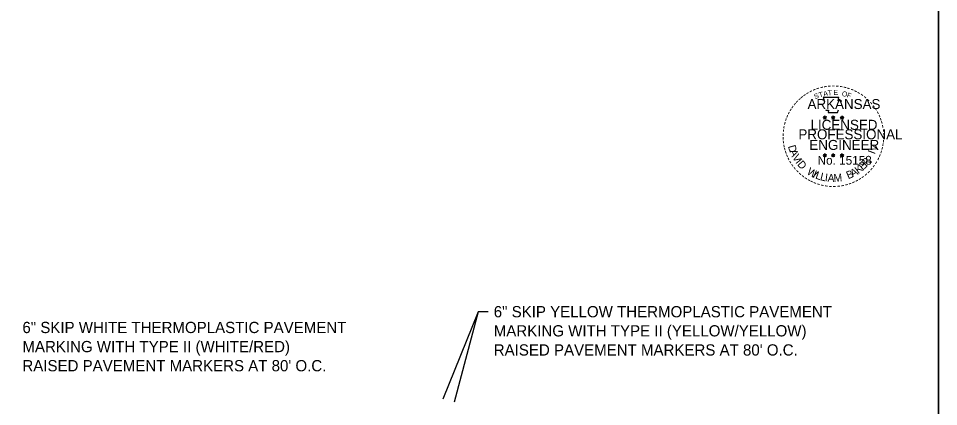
# Model space of a CAD drawing. Extents: x 1373096 to 1373266, y 381130 to 381790.
# Drawn here: x 1373174 to 1373266, y 381529.2 to 381568 of the extents above; entities that cross this region are included whole.
import ezdxf

# ---------------------------------------------------------------- set-up
doc = ezdxf.new("R2010")
doc.units = 0
for name, color, linetype in [('Default', 7, 'Continuous'), ('DSN_DRFT_Junk-No-Plot', 7, 'Continuous'), ('R_Border PE', 7, 'Continuous')]:
    doc.layers.add(name, color=color, linetype=linetype)

msp = doc.modelspace()

# ---------------------------------------------------------------- linework, layer by layer
at = {"layer": 'Default'}
for p, q in [((1373219.95, 381538.656), (1373216.424, 381529.917)), ((1373219.95, 381538.656), (1373217.551, 381529.618)), ((1373220.95, 381538.656), (1373219.95, 381538.656))]:
    msp.add_line(p, q, dxfattribs=at)
msp.add_lwpolyline([(1373095.974, 381570.174), (1373095.974, 381460.174), (1373265.974, 381460.174), (1373265.974, 381570.174)], close=True, dxfattribs=at)
at = {"layer": 'DSN_DRFT_Junk-No-Plot'}
for points in [[(1373095.974, 381570.174), (1373265.974, 381570.174), (1373265.974, 381460.174), (1373095.974, 381460.174)], [(1373095.974, 381570.174), (1373095.974, 381460.174), (1373265.974, 381460.174), (1373265.974, 381570.174)]]:
    msp.add_lwpolyline(points, close=True, dxfattribs=at)
at = {"layer": 'R_Border PE'}
for p, q in [((1373254.429, 381558.13), (1373254.603, 381558.074)), ((1373254.429, 381558.13), (1373254.555, 381558.107)), ((1373254.429, 381558.13), (1373254.547, 381558.069)), ((1373254.495, 381557.926), (1373254.603, 381558.074)), ((1373254.495, 381557.926), (1373254.558, 381558.048)), ((1373254.495, 381557.926), (1373254.602, 381558.034)), ((1373254.603, 381558.257), (1373254.583, 381558.131)), ((1373254.71, 381557.926), (1373254.602, 381558.033)), ((1373254.603, 381558.074), (1373254.603, 381558.257)), ((1373254.603, 381558.257), (1373254.628, 381558.132)), ((1373254.777, 381558.13), (1373254.603, 381558.074)), ((1373254.71, 381557.926), (1373254.603, 381558.074)), ((1373254.777, 381558.13), (1373254.634, 381558.105)), ((1373254.71, 381557.926), (1373254.641, 381558.071)), ((1373254.777, 381558.13), (1373254.675, 381558.079)), ((1373255.264, 381558.13), (1373255.438, 381558.074)), ((1373255.264, 381558.13), (1373255.39, 381558.107)), ((1373255.264, 381558.13), (1373255.382, 381558.069)), ((1373255.33, 381557.926), (1373255.438, 381558.074)), ((1373255.33, 381557.926), (1373255.393, 381558.048)), ((1373255.33, 381557.926), (1373255.437, 381558.034)), ((1373255.438, 381558.257), (1373255.418, 381558.131)), ((1373255.545, 381557.926), (1373255.437, 381558.033)), ((1373255.438, 381558.074), (1373255.438, 381558.257)), ((1373255.438, 381558.257), (1373255.463, 381558.132)), ((1373255.612, 381558.13), (1373255.438, 381558.074)), ((1373255.545, 381557.926), (1373255.438, 381558.074)), ((1373255.612, 381558.13), (1373255.469, 381558.105)), ((1373255.545, 381557.926), (1373255.476, 381558.071)), ((1373255.612, 381558.13), (1373255.51, 381558.079)), ((1373256.146, 381558.124), (1373256.32, 381558.068)), ((1373256.146, 381558.124), (1373256.272, 381558.101)), ((1373256.146, 381558.124), (1373256.264, 381558.063)), ((1373256.212, 381557.92), (1373256.32, 381558.068)), ((1373256.212, 381557.92), (1373256.275, 381558.042)), ((1373256.212, 381557.92), (1373256.319, 381558.028)), ((1373256.32, 381558.251), (1373256.3, 381558.125)), ((1373256.427, 381557.92), (1373256.319, 381558.027)), ((1373256.32, 381558.068), (1373256.32, 381558.251)), ((1373256.32, 381558.251), (1373256.345, 381558.126)), ((1373256.494, 381558.124), (1373256.32, 381558.068)), ((1373256.427, 381557.92), (1373256.32, 381558.068)), ((1373256.494, 381558.124), (1373256.351, 381558.099)), ((1373256.427, 381557.92), (1373256.358, 381558.065)), ((1373256.494, 381558.124), (1373256.392, 381558.073)), ((1373254.427, 381554.343), (1373254.601, 381554.288)), ((1373254.427, 381554.343), (1373254.553, 381554.321)), ((1373254.427, 381554.343), (1373254.545, 381554.282)), ((1373254.493, 381554.139), (1373254.601, 381554.288)), ((1373254.493, 381554.139), (1373254.556, 381554.261)), ((1373254.493, 381554.139), (1373254.6, 381554.248)), ((1373254.601, 381554.47), (1373254.581, 381554.344)), ((1373254.708, 381554.139), (1373254.6, 381554.246)), ((1373254.601, 381554.288), (1373254.601, 381554.47)), ((1373254.601, 381554.47), (1373254.626, 381554.345)), ((1373254.775, 381554.343), (1373254.601, 381554.288)), ((1373254.708, 381554.139), (1373254.601, 381554.288)), ((1373254.775, 381554.343), (1373254.632, 381554.319)), ((1373254.708, 381554.139), (1373254.639, 381554.285)), ((1373254.775, 381554.343), (1373254.673, 381554.292)), ((1373255.261, 381554.343), (1373255.436, 381554.288)), ((1373255.261, 381554.343), (1373255.388, 381554.321)), ((1373255.261, 381554.343), (1373255.38, 381554.282)), ((1373255.328, 381554.139), (1373255.436, 381554.288)), ((1373255.328, 381554.139), (1373255.391, 381554.261)), ((1373255.328, 381554.139), (1373255.435, 381554.248)), ((1373255.436, 381554.47), (1373255.415, 381554.344)), ((1373255.542, 381554.139), (1373255.435, 381554.246)), ((1373255.436, 381554.288), (1373255.436, 381554.47)), ((1373255.436, 381554.47), (1373255.46, 381554.345)), ((1373255.609, 381554.343), (1373255.436, 381554.288)), ((1373255.542, 381554.139), (1373255.436, 381554.288)), ((1373255.609, 381554.343), (1373255.466, 381554.319)), ((1373255.542, 381554.139), (1373255.474, 381554.285)), ((1373255.609, 381554.343), (1373255.507, 381554.292)), ((1373256.145, 381554.338), (1373256.319, 381554.283)), ((1373256.145, 381554.338), (1373256.271, 381554.316)), ((1373256.145, 381554.338), (1373256.263, 381554.277)), ((1373256.211, 381554.134), (1373256.319, 381554.283)), ((1373256.211, 381554.134), (1373256.274, 381554.256)), ((1373256.211, 381554.134), (1373256.318, 381554.243)), ((1373256.319, 381554.465), (1373256.299, 381554.339)), ((1373256.426, 381554.134), (1373256.318, 381554.241)), ((1373256.319, 381554.283), (1373256.319, 381554.465)), ((1373256.319, 381554.465), (1373256.344, 381554.34)), ((1373256.493, 381554.338), (1373256.319, 381554.283)), ((1373256.426, 381554.134), (1373256.319, 381554.283)), ((1373256.493, 381554.338), (1373256.35, 381554.314)), ((1373256.426, 381554.134), (1373256.357, 381554.28)), ((1373256.493, 381554.338), (1373256.391, 381554.287))]:
    msp.add_line(p, q, dxfattribs=at)
for points in [[(1373254.449, 381560.069), (1373254.584, 381559.655)], [(1373256.205, 381559.608), (1373256.276, 381559.75), (1373255.933, 381559.738), (1373256.007, 381560.069), (1373254.449, 381560.069)], [(1373254.695, 381558.857), (1373254.695, 381558.814), (1373254.977, 381558.804), (1373254.95, 381558.568), (1373255.885, 381558.568), (1373255.985, 381558.836)], [(1373254.603, 381558.257), (1373254.71, 381557.926), (1373254.429, 381558.13), (1373254.777, 381558.13), (1373254.495, 381557.926), (1373254.603, 381558.257)], [(1373255.438, 381558.257), (1373255.545, 381557.926), (1373255.264, 381558.13), (1373255.612, 381558.13), (1373255.33, 381557.926), (1373255.438, 381558.257)], [(1373256.32, 381558.251), (1373256.427, 381557.92), (1373256.146, 381558.124), (1373256.494, 381558.124), (1373256.212, 381557.92), (1373256.32, 381558.251)], [(1373254.601, 381554.47), (1373254.708, 381554.139), (1373254.427, 381554.343), (1373254.775, 381554.343), (1373254.493, 381554.139), (1373254.601, 381554.47)], [(1373255.436, 381554.47), (1373255.542, 381554.139), (1373255.261, 381554.343), (1373255.609, 381554.343), (1373255.328, 381554.139), (1373255.436, 381554.47)], [(1373256.319, 381554.465), (1373256.426, 381554.134), (1373256.145, 381554.338), (1373256.493, 381554.338), (1373256.211, 381554.134), (1373256.319, 381554.465)]]:
    msp.add_lwpolyline(points, dxfattribs=at)
for centre, radius in [((1373254.603, 381558.074), 0.0861), ((1373254.603, 381558.074), 0.0723), ((1373254.603, 381558.074), 0.0579), ((1373254.603, 381558.074), 0.0495), ((1373254.603, 381558.074), 0.0374), ((1373254.603, 381558.074), 0.0248), ((1373254.603, 381558.074), 0.0148), ((1373255.438, 381558.074), 0.0861), ((1373255.438, 381558.074), 0.0723), ((1373255.438, 381558.074), 0.0579), ((1373255.438, 381558.074), 0.0495), ((1373255.438, 381558.074), 0.0374), ((1373255.438, 381558.074), 0.0248), ((1373255.438, 381558.074), 0.0148), ((1373256.32, 381558.068), 0.0861), ((1373256.32, 381558.068), 0.0723), ((1373256.32, 381558.068), 0.0579), ((1373256.32, 381558.068), 0.0495), ((1373256.32, 381558.068), 0.0374), ((1373256.32, 381558.068), 0.0248), ((1373256.32, 381558.068), 0.0148), ((1373254.601, 381554.287), 0.0861), ((1373254.601, 381554.287), 0.0723), ((1373254.601, 381554.287), 0.0579), ((1373254.601, 381554.287), 0.0495), ((1373254.601, 381554.287), 0.0374), ((1373254.601, 381554.287), 0.0248), ((1373254.601, 381554.287), 0.0148), ((1373255.435, 381554.287), 0.0861), ((1373255.435, 381554.287), 0.0723), ((1373255.435, 381554.287), 0.0579), ((1373255.435, 381554.287), 0.0495), ((1373255.435, 381554.287), 0.0374), ((1373255.435, 381554.287), 0.0248), ((1373255.435, 381554.287), 0.0148), ((1373256.319, 381554.282), 0.0861), ((1373256.319, 381554.282), 0.0723), ((1373256.319, 381554.282), 0.0579), ((1373256.319, 381554.282), 0.0495), ((1373256.319, 381554.282), 0.0374), ((1373256.319, 381554.282), 0.0248), ((1373256.319, 381554.282), 0.0148)]:
    msp.add_circle(centre, radius, dxfattribs=at)

# ---------------------------------------------------------------- texts
at = {"layer": 'Default'}
for s, p in [('6" SKIP YELLOW THERMOPLASTIC PAVEMENT', (1373221.513, 381538.094)), ('6" SKIP WHITE THERMOPLASTIC PAVEMENT', (1373174.403, 381536.517)), ('MARKING WITH TYPE II (YELLOW/YELLOW)', (1373221.513, 381536.181)), ('MARKING WITH TYPE II (WHITE/RED)', (1373174.403, 381534.605)), ("RAISED PAVEMENT MARKERS AT 80' O.C.", (1373221.513, 381534.269)), ("RAISED PAVEMENT MARKERS AT 80' O.C.", (1373174.403, 381532.693))]:
    msp.add_text(s, height=1.125, dxfattribs=at).set_placement(p)
at = {"layer": 'R_Border PE'}
for s, height, rotation, p in [('-', 0.8, 19.17608, (1373253.823, 381560.632)), ('-', 0.8, 13.63015, (1373254.198, 381560.753)), ('-', 0.8, 10.21935, (1373254.537, 381560.834)), ('-', 0.8, 5.89682, (1373254.901, 381560.889)), ('-', 0.8, 0.18623, (1373255.287, 381560.925)), ('-', 0.8, 357.74304, (1373255.649, 381560.918)), ('-', 0.8, 352.16172, (1373256.021, 381560.89)), ('-', 0.8, 347.20489, (1373256.38, 381560.833)), ('-', 0.8, 342.3362, (1373256.698, 381560.756)), ('-', 0.8, 38.95066, (1373252.364, 381559.768)), ('-', 0.8, 36.23174, (1373252.602, 381559.957)), ('-', 0.8, 34.06357, (1373252.891, 381560.154)), ('-', 0.8, 28.79182, (1373253.189, 381560.339)), ('-', 0.8, 24.30721, (1373253.506, 381560.498)), ('S', 0.5, 21.59401, (1373253.626, 381559.908)), ('T', 0.5, 16.4036, (1373254.083, 381560.073)), ('A', 0.5, 11.21318, (1373254.496, 381560.199)), ('T', 0.5, 6.02276, (1373254.921, 381560.282)), ('E', 0.5, 0.83234, (1373255.473, 381560.337)), ('O', 0.5, 350.4515, (1373256.275, 381560.232)), ('F', 0.5, 340.07066, (1373256.752, 381560.118)), ('-', 0.8, 337.85509, (1373257.065, 381560.644)), ('-', 0.8, 334.12109, (1373257.381, 381560.509)), ('-', 0.8, 329.64089, (1373257.67, 381560.367)), ('-', 0.8, 325.86266, (1373257.992, 381560.187)), ('-', 0.8, 320.52971, (1373258.297, 381559.974)), ('-', 0.8, 54.23247, (1373251.515, 381558.794)), ('-', 0.8, 50.61418, (1373251.722, 381559.077)), ('-', 0.8, 48.42305, (1373251.923, 381559.32)), ('-', 0.8, 42.96224, (1373252.147, 381559.559)), ('-', 0.8, 315.57859, (1373258.596, 381559.73)), ('-', 0.8, 309.87973, (1373258.881, 381559.455)), ('-', 0.8, 306.65218, (1373259.143, 381559.154)), ('-', 0.8, 67.77427, (1373251.067, 381557.918)), ('-', 0.8, 62.87135, (1373251.196, 381558.223)), ('-', 0.8, 58.07063, (1373251.353, 381558.53)), ('-', 0.7, 303.67529, (1373259.386, 381558.87)), ('-', 0.8, 299.66835, (1373259.546, 381558.566)), ('-', 0.8, 294.66279, (1373259.708, 381558.26)), ('-', 0.8, 75.46096, (1373250.859, 381557.246)), ('-', 0.8, 72.39447, (1373250.957, 381557.603)), ('-', 0.8, 290.57283, (1373259.836, 381557.972)), ('-', 0.8, 285.12326, (1373259.953, 381557.682)), ('-', 0.8, 89.06224, (1373250.742, 381556.193)), ('-', 0.8, 85.18634, (1373250.755, 381556.544)), ('-', 0.8, 81.20126, (1373250.793, 381556.889)), ('-', 0.8, 280.54934, (1373260.053, 381557.311)), ('-', 0.8, 276.59616, (1373260.134, 381556.927)), ('-', 0.8, 274.33011, (1373260.164, 381556.566)), ('-', 0.8, 94.19588, (1373250.76, 381555.831)), ('-', 0.8, 98.94793, (1373250.796, 381555.497)), ('-', 0.8, 263.5172, (1373260.172, 381555.917)), ('-', 0.8, 269.94067, (1373260.181, 381556.25)), ('-', 0.8, 101.71495, (1373250.863, 381555.131)), ('-', 0.8, 105.45785, (1373250.944, 381554.833)), ('-', 0.8, 109.08742, (1373251.052, 381554.518)), ('D', 0.77, 286.28478, (1373250.908, 381555.2)), ('A', 0.77, 292.78351, (1373251.054, 381554.699)), ('I', 0.77, 69.03009, (1373259.593, 381554.35)), ('V', 0.77, 72.65729, (1373259.704, 381554.619)), ('-', 0.8, 252.86809, (1373259.991, 381554.891)), ('-', 0.8, 255.7626, (1373260.081, 381555.251)), ('-', 0.8, 260.99529, (1373260.136, 381555.59)), ('-', 0.8, 114.06432, (1373251.179, 381554.22)), ('-', 0.8, 115.72885, (1373251.331, 381553.911)), ('-', 0.8, 120.44712, (1373251.51, 381553.618)), ('V', 0.77, 300.79357, (1373251.311, 381554.109)), ('I', 0.77, 308.35023, (1373251.627, 381553.591)), ('D', 0.77, 311.97742, (1373251.802, 381553.358)), ('E', 0.77, 44.01755, (1373258.4, 381552.752)), ('R', 0.77, 50.36514, (1373258.768, 381553.105)), (',', 0.77, 57.4684, (1373259.129, 381553.547)), ('-', 0.8, 244.61971, (1373259.748, 381554.24)), ('-', 0.8, 247.88866, (1373259.879, 381554.554)), ('-', 0.8, 125.89344, (1373251.711, 381553.337)), ('-', 0.8, 130.71812, (1373251.942, 381553.061)), ('-', 0.8, 134.22381, (1373252.201, 381552.789)), ('W', 0.77, 328.07311, (1373252.741, 381552.475)), ('I', 0.77, 336.6877, (1373253.335, 381552.12)), ('B', 0.77, 22.8589, (1373256.939, 381551.901)), ('A', 0.77, 28.90423, (1373257.387, 381552.088)), ('K', 0.77, 36.91429, (1373257.946, 381552.407)), ('-', 0.8, 231.25377, (1373259.135, 381553.254)), ('-', 0.8, 233.84524, (1373259.35, 381553.537)), ('-', 0.8, 239.07125, (1373259.551, 381553.864)), ('-', 0.8, 138.93382, (1373252.463, 381552.557)), ('-', 0.8, 144.64634, (1373252.741, 381552.354)), ('-', 0.8, 148.08978, (1373253.022, 381552.168)), ('-', 0.8, 151.57039, (1373253.311, 381552.006)), ('L', 0.77, 340.3149, (1373253.6, 381551.998)), ('L', 0.77, 346.66249, (1373254.079, 381551.826)), ('I', 0.77, 353.01009, (1373254.575, 381551.707)), ('A', 0.77, 356.63729, (1373254.864, 381551.665)), ('M', 0.77, 4.64735, (1373255.506, 381551.636)), ('-', 0.8, 207.35684, (1373257.814, 381552.115)), ('-', 0.8, 212.24909, (1373258.093, 381552.288)), ('-', 0.8, 215.73633, (1373258.36, 381552.482)), ('-', 0.8, 221.08509, (1373258.635, 381552.718)), ('-', 0.8, 225.76533, (1373258.896, 381552.972)), ('-', 0.8, 154.60019, (1373253.572, 381551.882)), ('-', 0.8, 158.56121, (1373253.884, 381551.755)), ('-', 0.8, 162.79826, (1373254.228, 381551.649)), ('-', 0.8, 167.55551, (1373254.585, 381551.567)), ('-', 0.8, 173.11546, (1373254.971, 381551.512)), ('-', 0.8, 176.51827, (1373255.345, 381551.485)), ('-', 0.8, 181.59176, (1373255.717, 381551.495)), ('-', 0.8, 185.81666, (1373256.122, 381551.533)), ('-', 0.8, 191.28576, (1373256.49, 381551.599)), ('-', 0.8, 195.47429, (1373256.854, 381551.698)), ('-', 0.8, 199.46435, (1373257.187, 381551.817)), ('-', 0.8, 204.25161, (1373257.502, 381551.956))]:
    msp.add_text(s, height=height, rotation=rotation, dxfattribs=at).set_placement(p)
for s, height, p in [('ARKANSAS', 1, (1373252.875, 381558.925)), ('LICENSED', 1, (1373253.174, 381556.85)), ('PROFESSIONAL', 1, (1373251.962, 381555.898)), ('ENGINEER', 1, (1373253.056, 381554.836)), ('No. 15158', 0.8785, (1373253.877, 381553.36)), ('AAMU', 0.00001, (1373255.402, 381551.633))]:
    msp.add_text(s, height=height, dxfattribs=at).set_placement(p)

doc.saveas('drawing.dxf')
